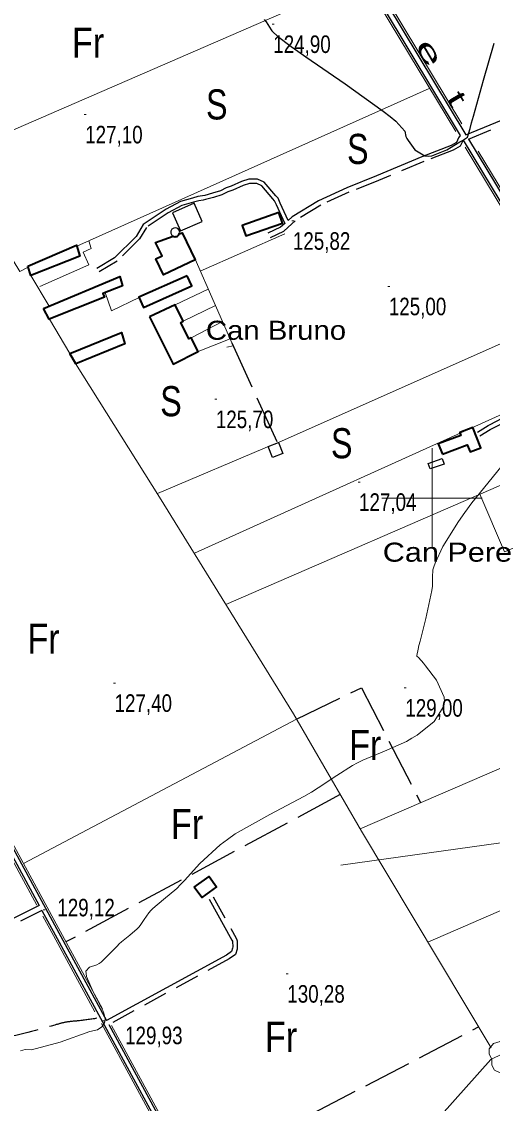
# Model space of a CAD drawing. Extents: x 487425 to 492029, y 4383576 to 4386788.
# Drawn here: x 488796 to 489030, y 4384698 to 4385238 of the extents above; entities that cross this region are included whole.
import ezdxf
from ezdxf.enums import TextEntityAlignment as Align

# ---------------------------------------------------------------- set-up
doc = ezdxf.new("R2010")
doc.units = 0
doc.header["$LTSCALE"] = 4
doc.linetypes.add('LONG_DASHED', pattern=[7.5, 6, -1.5])
doc.linetypes.add('MEDIUM_DASHED', pattern=[4.5, 3, -1.5])
for name, color, linetype, lineweight in [('1', 7, 'Continuous', 13), ('21', 7, 'Continuous', 25), ('24', 7, 'Continuous', 13), ('25', 7, 'LONG_DASHED', 25), ('29', 7, 'Continuous', 13), ('38', 7, 'Continuous', 25), ('47', 7, 'Continuous', 35), ('48', 7, 'MEDIUM_DASHED', 25), ('51', 7, 'Continuous', 13), ('7', 7, 'Continuous', 13), ('8', 7, 'Continuous', 25), ('9', 7, 'Continuous', 13)]:
    doc.layers.add(name, color=color, linetype=linetype, lineweight=lineweight)
doc.layers.add('31', color=7, linetype='Continuous')
doc.layers.add('5', color=7, linetype='Continuous')

msp = doc.modelspace()

# ---------------------------------------------------------------- linework, layer by layer
at = {"layer": '1'}
for p, q in [((489000, 4385025), (489000, 4384975)), ((488975, 4385000), (489025, 4385000))]:
    msp.add_line(p, q, dxfattribs=at)
at = {"layer": '21'}
for points in [[(488881.44, 4385147.02), (488870.65, 4385142.32), (488874.61, 4385133.22), (488885.4, 4385137.92)], [(488874.3, 4385132.6), (488874.04, 4385133.63), (488873.34, 4385134.42), (488872.35, 4385134.8), (488871.29, 4385134.67), (488870.42, 4385134.07), (488869.92, 4385133.13), (488869.92, 4385132.07), (488870.42, 4385131.12), (488871.29, 4385130.52), (488872.35, 4385130.39), (488873.34, 4385130.77)], [(488997.97, 4385017.33), (489004.94, 4385019.79), (489005.92, 4385017.01), (488998.95, 4385014.55)]]:
    msp.add_lwpolyline(points, close=True, dxfattribs=at)
at = {"layer": '24'}
msp.add_lwpolyline([(488954.49, 4384817.11), (489198.5, 4384851.16), (489357.39, 4384873.86), (489601.4, 4384907.91), (489794.34, 4384879.53), (490083.75, 4384822.79), (490248.31, 4384800.09), (490395.85, 4384817.11), (490526.37, 4384822.79), (490764.71, 4384947.63), (491088.16, 4385117.87), (491252.72, 4385202.99), (491256.7, 4385199.2)], dxfattribs=at)
at = {"layer": '25'}
for p, q in [((488900.24, 4385077.39), (488922.96, 4385027.59)), ((488954.25, 4384852.26), (488817.62, 4384778.81)), ((488887.29, 4384665.46), (489023.14, 4384736.42))]:
    msp.add_line(p, q, dxfattribs=at)
msp.add_lwpolyline([(488932.52, 4384889.8), (488964.74, 4384905.47), (488994.23, 4384848.26)], dxfattribs=at)
at = {"layer": '29'}
msp.add_lwpolyline([(489035.67, 4384712.77), (489031.13, 4384714.89), (489029.72, 4384717.43), (489029.82, 4384720.41), (489028.45, 4384722.82), (489028.49, 4384725.57), (489030.65, 4384728.17), (489033.84, 4384729.17), (489035.49, 4384731.36), (489038.06, 4384732.19), (489040.92, 4384731.54), (489042.87, 4384729.27), (489045.68, 4384728.45), (489047.81, 4384725.6), (489048.05, 4384722.47), (489046.17, 4384719.32), (489046.17, 4384716.64), (489044.35, 4384714.03), (489040.73, 4384712.69), (489037.96, 4384713.32)], close=True, dxfattribs=at)
at = {"layer": '38'}
for points in [[(488878.73, 4385407.09), (488921.18, 4385336.61), (488975.13, 4385245.45), (489014.03, 4385180.84)], [(488514.64, 4385338.17), (488603.76, 4385173.21), (488658.8, 4385071.45), (488744.97, 4384910.75), (488814.04, 4384783.4), (488837.88, 4384739.61)], [(488960.62, 4385274.92), (488977.3, 4385246.74), (489016.84, 4385181.06)], [(489016.84, 4385181.06), (489055.91, 4385197.29), (489073.55, 4385205.37), (489076.97, 4385207.46), (489080.73, 4385211.27)], [(489014.03, 4385180.84), (489013.21, 4385179.56), (489012.09, 4385177.3), (489009.43, 4385175.77), (488994.86, 4385170.18), (488972.32, 4385160.61), (488957.54, 4385154.77), (488943.44, 4385148.3), (488930.34, 4385140.27), (488928.32, 4385138.49)], [(489015.44, 4385178.51), (489052.45, 4385117.1), (489083.74, 4385064.9), (489085.54, 4385061.96)], [(489018.13, 4385178.93), (489054.61, 4385118.4), (489085.9, 4385066.21), (489107.63, 4385030.7), (489130.24, 4384993.46), (489150.71, 4384958.9)], [(488928.32, 4385138.49), (488924.34, 4385147.12), (488923.31, 4385149.48), (488922.16, 4385150.65), (488916.42, 4385157.46), (488913.09, 4385159.05), (488908.7, 4385159.02), (488905.1, 4385157.86), (488899.89, 4385155.59), (488897.38, 4385154.71), (488894.52, 4385153.24), (488890.56, 4385151.98), (488886.72, 4385150.92), (488885.57, 4385150.72), (488883.34, 4385150.36), (488880.57, 4385149.54), (488874.59, 4385147.86), (488867.49, 4385144.03), (488856.14, 4385136.49), (488852.57, 4385130.52), (488841.75, 4385119.87), (488833.02, 4385114.56)], [(488926.66, 4385137.04), (488926.56, 4385136.95), (488924.52, 4385135.04), (488918.24, 4385132.1)], [(489022.61, 4385032.92), (489027.86, 4385036.18), (489032.79, 4385038.76), (489039.38, 4385042.38), (489047.35, 4385045.99), (489062.52, 4385052.43), (489074.96, 4385057.76), (489085.54, 4385061.96)], [(488719.59, 4384953.71), (488743.15, 4384909.76), (488804.31, 4384796.99)], [(488888.93, 4384800.09), (488900.31, 4384779.74), (488900.5, 4384779.2), (488900.56, 4384778.97), (488900.66, 4384776.28), (488900.59, 4384775.77), (488900.04, 4384774.02), (488897.62, 4384772.28), (488837.88, 4384739.61)], [(488804.31, 4384796.99), (488751.59, 4384770.9), (488728.41, 4384758.11), (488701.12, 4384744.55), (488690.36, 4384739.26), (488688.39, 4384738.87), (488685.81, 4384738.9), (488683.88, 4384739.3), (488677.49, 4384746.56)], [(488805.65, 4384794.52), (488812.22, 4384782.41), (488869.76, 4384676.73), (488872.68, 4384671.28)], [(488838.98, 4384737.59), (488871.58, 4384677.72), (488879.96, 4384662.05)]]:
    msp.add_lwpolyline(points, dxfattribs=at)
at = {"layer": '38', "linetype": 'MEDIUM_DASHED'}
for points in [[(489018.13, 4385178.93), (489056.89, 4385195.04), (489074.71, 4385203.2), (489078.51, 4385205.52), (489082.48, 4385209.55)], [(489015.44, 4385178.51), (489013.97, 4385175.53), (489010.5, 4385173.53), (488995.79, 4385167.89), (488973.26, 4385158.32), (488958.51, 4385152.5), (488944.6, 4385146.12), (488931.81, 4385138.28), (488928.22, 4385135.12), (488925.92, 4385132.97), (488919.29, 4385129.86)], [(488926.66, 4385137.04), (488922.41, 4385146.26), (488921.53, 4385148.28), (488920.6, 4385149.23), (488915.1, 4385155.75), (488912.61, 4385156.93), (488909.04, 4385156.91), (488905.85, 4385155.88), (488900.67, 4385153.62), (488898.22, 4385152.76), (488895.33, 4385151.28), (488891.16, 4385149.95), (488887.18, 4385148.85), (488885.92, 4385148.63), (488883.8, 4385148.29), (488881.15, 4385147.51), (488875.39, 4385145.89), (488868.58, 4385142.21), (488857.71, 4385134.99), (488854.25, 4385129.2), (488843.06, 4385118.19), (488834.12, 4385112.75)], [(489023.8, 4385031.01), (489028.97, 4385034.23), (489033.86, 4385036.78), (489040.39, 4385040.37), (489048.26, 4385043.93), (489063.4, 4385050.36), (489075.82, 4385055.68), (489086.73, 4385060.01)], [(488890.93, 4384801.21), (488902.41, 4384780.69), (488902.69, 4384779.87), (488902.84, 4384779.31), (488902.97, 4384776.18), (488902.84, 4384775.26), (488901.99, 4384772.6), (488898.85, 4384770.33), (488838.98, 4384737.59)], [(488805.65, 4384794.52), (488752.89, 4384768.41), (488729.72, 4384755.62), (488702.37, 4384742.03), (488691.27, 4384736.57), (488688.65, 4384736.05), (488685.51, 4384736.09), (488682.39, 4384736.73), (488675.37, 4384744.7)]]:
    msp.add_lwpolyline(points, dxfattribs=at)
at = {"layer": '38', "linetype": 'LONG_DASHED'}
msp.add_spline([(488833, 4384740.72), (488823.16, 4384739.41), (488817.75, 4384738.8), (488812.11, 4384737.36), (488780.89, 4384729.91), (488765.32, 4384726.57), (488755.29, 4384722.03), (488743.94, 4384719.31), (488733.73, 4384718.9)], degree=3, dxfattribs=at)
at = {"layer": '47'}
for points in [[(488923.7, 4385142.33), (488905.33, 4385135.99), (488907.14, 4385130.74), (488925.51, 4385137.08)], [(488798.56, 4385115.7), (488822.91, 4385126.08), (488824.5, 4385120.66), (488800.08, 4385111.03)], [(488806.42, 4385094.53), (488844.41, 4385110.45), (488845.71, 4385105.86), (488835.99, 4385102), (488836.87, 4385100.26), (488809.21, 4385089.17)], [(488877.95, 4385110.9), (488853.96, 4385100.21), (488856.24, 4385095.09), (488880.23, 4385105.78)], [(488859.19, 4385090.48), (488871, 4385066.86), (488883.39, 4385073.07), (488879.9, 4385080.01), (488878.85, 4385079.49), (488874.83, 4385087.59), (488876.01, 4385088.17), (488871.94, 4385096.44)], [(488819.52, 4385072.17), (488845.22, 4385082.53), (488846.88, 4385076.89), (488822.46, 4385067.04)], [(489005.23, 4385021.9), (489017.51, 4385026.63), (489018.89, 4385023.02), (489024.23, 4385025.08), (489020.29, 4385035.28), (489013.72, 4385032.75), (489014.27, 4385031.29), (489002.93, 4385027.02)], [(488881.54, 4384806.12), (488888.9, 4384811.45), (488892.64, 4384806.29), (488885.28, 4384800.96)]]:
    msp.add_lwpolyline(points, close=True, dxfattribs=at)
msp.add_lwpolyline([(488874.05, 4385131.69), (488875.57, 4385132.23), (488882.02, 4385118.88), (488866.24, 4385111.26), (488862.34, 4385119.31), (488865.51, 4385120.84), (488862.29, 4385127.49), (488871, 4385130.6)], dxfattribs=at)
msp.add_ellipse((488872.09, 4385132.36), major_axis=(1.99, 0.71), ratio=0.948762, start_param=3.839059, end_param=5.585719, dxfattribs=at)
at = {"layer": '48'}
msp.add_lwpolyline([(488920.44, 4385020.31), (488918.32, 4385025.79), (488923.45, 4385027.78), (488925.57, 4385022.3)], close=True, dxfattribs=at)
at = {"layer": '51'}
for p, q in [((488760.12, 4385169.94), (488965.78, 4385259.45)), ((488823.1, 4385125.7), (488998.6, 4385204.2)), ((488884.49, 4385113.24), (488926.58, 4385131.72)), ((488800.08, 4385111.03), (488809.31, 4385095.74)), ((488871.94, 4385096.44), (488888.45, 4385104.24)), ((488876.01, 4385088.17), (488892.07, 4385095.99)), ((488923.45, 4385027.78), (489066.7, 4385091.55)), ((488809.39, 4385089.25), (488819.52, 4385072.17)), ((488879.9, 4385080.01), (488895.57, 4385088.02)), ((488883.39, 4385073.07), (488899.36, 4385079.38)), ((488881.68, 4384972.61), (489082.99, 4385063.75)), ((488897.28, 4384947.05), (489100.68, 4385035.46)), ((488863.17, 4385002.26), (488921.2, 4385026.91)), ((488964.11, 4384835.23), (489168.09, 4384923.44)), ((488932.46, 4384889.91), (488796.39, 4384817.93)), ((488997.94, 4384778.6), (489201.96, 4384868.29))]:
    msp.add_line(p, q, dxfattribs=at)
for points in [[(488880.65, 4385400.9), (488920.39, 4385336.14), (488974.34, 4385244.98), (489011.77, 4385182.82)], [(488798.74, 4385115.18), (488794.7, 4385112.97), (488725.77, 4385226.51), (488646.35, 4385359.77)], [(488518.06, 4385334.28), (488604.59, 4385173.66), (488659.63, 4385071.9), (488745.8, 4384911.2), (488814.87, 4384783.85), (488835.8, 4384745.42)], [(488962.66, 4385273.68), (488978.26, 4385247.31), (489014.79, 4385186.66)], [(489016.46, 4385175.04), (489051.66, 4385116.63), (489083.25, 4385063.95)], [(489023, 4385173.03), (489055.57, 4385118.98), (489086.86, 4385066.79), (489108.58, 4385031.28), (489131.2, 4384994.03), (489151.29, 4384960.14)], [(488622.46, 4385132.23), (488656.11, 4385070), (488742.28, 4384909.3), (488803.09, 4384797.19)], [(488804.67, 4385105.57), (488828.95, 4385116.33), (488826.17, 4385122.59), (488830.24, 4385124.49), (488829, 4385128.34)], [(488881.89, 4385119.16), (488900.89, 4385075.9), (488897.73, 4385075.26)], [(488854.03, 4385100.06), (488840.24, 4385093.47), (488837.11, 4385102.45)], [(488822.4, 4385067.16), (488864.24, 4385000.54), (488930.91, 4384892.58), (488964.83, 4384833.98), (489029.39, 4384725.96)], [(489023.81, 4385002.05), (489036.03, 4384973.23), (489117.27, 4385008.2)], [(489236.25, 4384810.18), (489166.41, 4384781.27), (489097.95, 4384751.06), (489041.4, 4384725.82), (489034.99, 4384723.05), (489029.25, 4384720.11), (488992.32, 4384678.89), (488988.14, 4384673.77), (488987.22, 4384672.28), (488986.75, 4384670.86), (488986.18, 4384666.51), (488986, 4384631.03), (488986.04, 4384627.95), (488986.39, 4384625.4), (488986.66, 4384623.37), (489008.55, 4384574.95)], [(488806.1, 4384791.63), (488811.35, 4384781.94), (488832.06, 4384743.93)], [(488835.25, 4384738.06), (488868.89, 4384676.27), (488871.18, 4384672.01)], [(488840.31, 4384737.13), (488872.41, 4384678.17), (488879.77, 4384664.44)]]:
    msp.add_lwpolyline(points, dxfattribs=at)
at = {"layer": '7'}
for p, q in [((488920.37, 4385236.29), (488921.37, 4385236.29)), ((488826.68, 4385191.22), (488827.68, 4385191.22)), ((488930.13, 4385138.2), (488931.13, 4385138.2)), ((488977.92, 4385105.55), (488978.92, 4385105.55)), ((488891.76, 4385049.29), (488892.76, 4385049.29)), ((488963.08, 4385008.04), (488964.08, 4385008.04)), ((488841.31, 4384907.85), (488842.31, 4384907.85)), ((488986.15, 4384905.45), (488987.15, 4384905.45)), ((488806.34, 4384794.81), (488807.34, 4384794.81)), ((488927.36, 4384762.9), (488928.36, 4384762.9)), ((488835.94, 4384739.41), (488836.94, 4384739.41))]:
    msp.add_line(p, q, dxfattribs=at)
at = {"layer": '8'}
msp.add_lwpolyline([(488916.35, 4385238.64), (488917.34, 4385237.41), (488919.06, 4385234.82), (488919.83, 4385233.46), (488920.22, 4385232.99), (488920.67, 4385232.49), (488922.95, 4385230.33), (488929.79, 4385225.21), (488933.12, 4385222.83), (488937.09, 4385220.03), (488956.61, 4385206.48), (488975.54, 4385192.97), (488979.12, 4385190.21), (488981.99, 4385187.87), (488986.38, 4385182.96), (488986.97, 4385180.24), (488987.45, 4385179.28), (488988.06, 4385178.23), (488991.41, 4385173.72), (488996.42, 4385170.61), (488998.08, 4385170.45), (488999.85, 4385170.59), (489007.25, 4385173.6), (489013.82, 4385177.62), (489015.07, 4385178.38), (489016.08, 4385179), (489017.68, 4385179.98), (489017.68, 4385179.98), (489017.68, 4385179.98), (489017.68, 4385179.98), (489017.68, 4385179.98), (489018.88, 4385184.33), (489019.65, 4385187.08), (489020.59, 4385190.5), (489025.56, 4385208.41), (489030.96, 4385226.81)], dxfattribs=at)
at = {"layer": '9'}
for points in [[(488994.73, 4384918.94), (488993, 4384920.82), (488992.58, 4384921.06), (488992.5, 4384921.15), (488992.43, 4384921.24), (488992.33, 4384921.65), (488993.02, 4384924.75), (488993.45, 4384926.53), (488993.98, 4384928.73), (488996.79, 4384940), (488999.43, 4384951.61), (488999.86, 4384954.02), (489000.16, 4384956.07), (489000.15, 4384960.56), (489000.43, 4384964.26), (489000.91, 4384965.82), (489001.57, 4384967.6), (489005.4, 4384975.97), (489013.16, 4384988.45), (489016.29, 4384992.83), (489019.86, 4384997.61), (489036.3, 4385018.19)], [(488795.03, 4384724.44), (488797.25, 4384725.24), (488800.42, 4384725.08), (488814.67, 4384728.88), (488829.56, 4384734.11), (488833.37, 4384735.06), (488835.42, 4384736.49), (488836.84, 4384738.46), (488836.89, 4384738.74), (488836.93, 4384738.92), (488836.98, 4384739.14), (488837.22, 4384740.28), (488836.48, 4384743.25), (488835.92, 4384744.62), (488835.19, 4384746.22), (488831.23, 4384754), (488827.92, 4384761.55), (488827.6, 4384763.02), (488827.53, 4384764.22), (488829.42, 4384766.28), (488833.06, 4384767.41), (488834.09, 4384768.02), (488835.14, 4384768.75), (488839.03, 4384772.46), (488843.04, 4384776.72), (488844.16, 4384777.79), (488845.3, 4384778.83), (488849.47, 4384782.19), (488853.12, 4384785.26), (488853.93, 4384786.11), (488854.65, 4384786.95), (488856.54, 4384789.99), (488858.83, 4384793.34), (488859.81, 4384794.39), (488860.93, 4384795.49), (488866.22, 4384799.87), (488872.8, 4384805.5), (488874.73, 4384807.38), (488876.71, 4384809.39), (488884.27, 4384817.83), (488894.41, 4384827.28), (488898.02, 4384829.93), (488901.97, 4384832.6), (488919.12, 4384842.37), (488936.06, 4384851.34), (488939.87, 4384853.51), (488943.31, 4384855.54), (488952.55, 4384861.72), (488960.3, 4384866.81), (488962.79, 4384868.14), (488965.43, 4384869.45), (488976.22, 4384873.9), (488987.18, 4384878.74), (488989.92, 4384880.29), (488992.55, 4384881.94), (489000.99, 4384888.65), (489005.82, 4384896.26), (489006.17, 4384898.48), (489006.08, 4384900.74), (489002.2, 4384909.29), (488996.73, 4384916.44), (488995.64, 4384917.82), (488994.73, 4384918.94)]]:
    msp.add_lwpolyline(points, dxfattribs=at)

# ---------------------------------------------------------------- texts
at = {"layer": '31'}
for s, width, p in [('Fr', 0.85, (488828.64, 4385219.61)), ('S', 0.8, (488892.72, 4385188.79)), ('S', 0.8, (488962.97, 4385166.6)), ('S', 0.8, (488869.93, 4385040.85)), ('S', 0.8, (488954.97, 4385019.89)), ('Fr', 0.85, (488806.46, 4384922.49)), ('Fr', 0.85, (488966.66, 4384869.48)), ('Fr', 0.85, (488877.93, 4384830.03)), ('Fr', 0.85, (488924.76, 4384724))]:
    msp.add_text(s, height=15, dxfattribs=dict(at, width=width)).set_placement(p, align=Align.CENTER)
at = {"layer": '5'}
for s, rotation, width, p in [('e', 300.532, 1.9, (488994.66, 4385219.75)), ('t', 300.779, 1.75, (489008.31, 4385196.82))]:
    msp.add_text(s, height=9.49, rotation=rotation, dxfattribs=dict(at, width=width)).set_placement(p, align=Align.CENTER)
for s, width, p in [('Can Bruno', 1.15, (488887.31, 4385078.95)), ('Can Pere', 1.2, (488975.41, 4384968.33))]:
    msp.add_text(s, height=9.5, dxfattribs=dict(at, width=width)).set_placement(p)
at = {"layer": '7', "width": 0.8}
for s, p in [('124,90', (488920.87, 4385221.92)), ('127,10', (488827.18, 4385176.85)), ('125,82', (488930.63, 4385123.83)), ('125,00', (488978.42, 4385091.18)), ('125,70', (488892.26, 4385034.92)), ('127,04', (488963.58, 4384993.67)), ('127,40', (488841.81, 4384893.48)), ('129,00', (488986.65, 4384891.08)), ('129,12', (488813.31, 4384791.54)), ('130,28', (488927.86, 4384748.53)), ('129,93', (488847.07, 4384727.81))]:
    msp.add_text(s, height=8.75, dxfattribs=at).set_placement(p)

doc.saveas('drawing.dxf')
